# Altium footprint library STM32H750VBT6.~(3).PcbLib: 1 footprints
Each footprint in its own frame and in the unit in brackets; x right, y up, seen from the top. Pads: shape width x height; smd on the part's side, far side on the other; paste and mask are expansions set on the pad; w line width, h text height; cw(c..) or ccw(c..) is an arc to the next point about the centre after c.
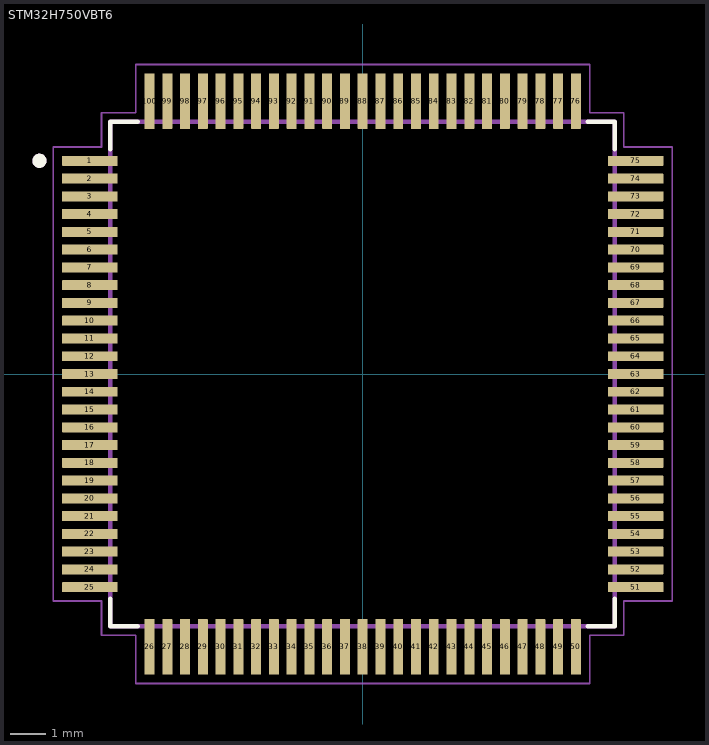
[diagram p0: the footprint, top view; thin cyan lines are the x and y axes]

## STM32H750VBT6 [mm]
pads (100):
  rrect7% 1.56x0.28 smd: 1(-7.68,6) 2(-7.68,5.5) 3(-7.68,5) 4(-7.68,4.5) 5(-7.68,4) 6(-7.68,3.5) 7(-7.68,3) 8(-7.68,2.5) 9(-7.68,2) 10(-7.68,1.5) 11(-7.68,1) 12(-7.68,0.5) 13(-7.68,0) 14(-7.68,-0.5) 15(-7.68,-1) 16(-7.68,-1.5) 17(-7.68,-2) 18(-7.68,-2.5) 19(-7.68,-3) 20(-7.68,-3.5) 21(-7.68,-4) 22(-7.68,-4.5) 23(-7.68,-5) 24(-7.68,-5.5) 25(-7.68,-6) 51(7.68,-6) 52(7.68,-5.5) 53(7.68,-5) 54(7.68,-4.5) 55(7.68,-4) 56(7.68,-3.5) 57(7.68,-3) 58(7.68,-2.5) 59(7.68,-2) 60(7.68,-1.5) 61(7.68,-1) 62(7.68,-0.5) 63(7.68,0) 64(7.68,0.5) 65(7.68,1) 66(7.68,1.5) 67(7.68,2) 68(7.68,2.5) 69(7.68,3) 70(7.68,3.5) 71(7.68,4) 72(7.68,4.5) 73(7.68,5) 74(7.68,5.5) 75(7.68,6)
  rrect7% 0.28x1.56 smd: 26(-6,-7.68) 27(-5.5,-7.68) 28(-5,-7.68) 29(-4.5,-7.68) 30(-4,-7.68) 31(-3.5,-7.68) 32(-3,-7.68) 33(-2.5,-7.68) 34(-2,-7.68) 35(-1.5,-7.68) 36(-1,-7.68) 37(-0.5,-7.68) 38(0,-7.68) 39(0.5,-7.68) 40(1,-7.68) 41(1.5,-7.68) 42(2,-7.68) 43(2.5,-7.68) 44(3,-7.68) 45(3.5,-7.68) 46(4,-7.68) 47(4.5,-7.68) 48(5,-7.68) 49(5.5,-7.68) 50(6,-7.68) 76(6,7.68) 77(5.5,7.68) 78(5,7.68) 79(4.5,7.68) 80(4,7.68) 81(3.5,7.68) 82(3,7.68) 83(2.5,7.68) 84(2,7.68) 85(1.5,7.68) 86(1,7.68) 87(0.5,7.68) 88(0,7.68) 89(-0.5,7.68) 90(-1,7.68) 91(-1.5,7.68) 92(-2,7.68) 93(-2.5,7.68) 94(-3,7.68) 95(-3.5,7.68) 96(-4,7.68) 97(-4.5,7.68) 98(-5,7.68) 99(-5.5,7.68) 100(-6,7.68)
Top Overlay:
  circle w0.2: c-9.1,6 r0.1
  lines w0.127: -7.1,-6.33 -7.1,-7.1 -6.33,-7.1 ; -7.1,6.33 -7.1,7.1 -6.33,7.1 ; 6.33,-7.1 7.1,-7.1 7.1,-6.33 ; 6.33,7.1 7.1,7.1 7.1,6.33
Mechanical 13:
  circle w0.2: c-9.1,6 r0.1
  lines w0.127: -7.1,-7.1 7.1,-7.1 7.1,7.1 -7.1,7.1 -7.1,-7.1
Mechanical 15:
  lines w0.05: -8.71,-6.39 -8.71,6.39 -7.35,6.39 -7.35,7.35 -6.39,7.35 -6.39,8.71 6.39,8.71 6.39,7.35 7.35,7.35 7.35,6.39 8.71,6.39 8.71,-6.39 7.35,-6.39 7.35,-7.35 6.39,-7.35 6.39,-8.71 -6.39,-8.71 -6.39,-7.35 -7.35,-7.35 -7.35,-6.39 -8.71,-6.39
3D body "STM32H750VBT6.STEP": height 1.49, standoff -0.11, extent -8.004,-7.999 7.996,8.001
